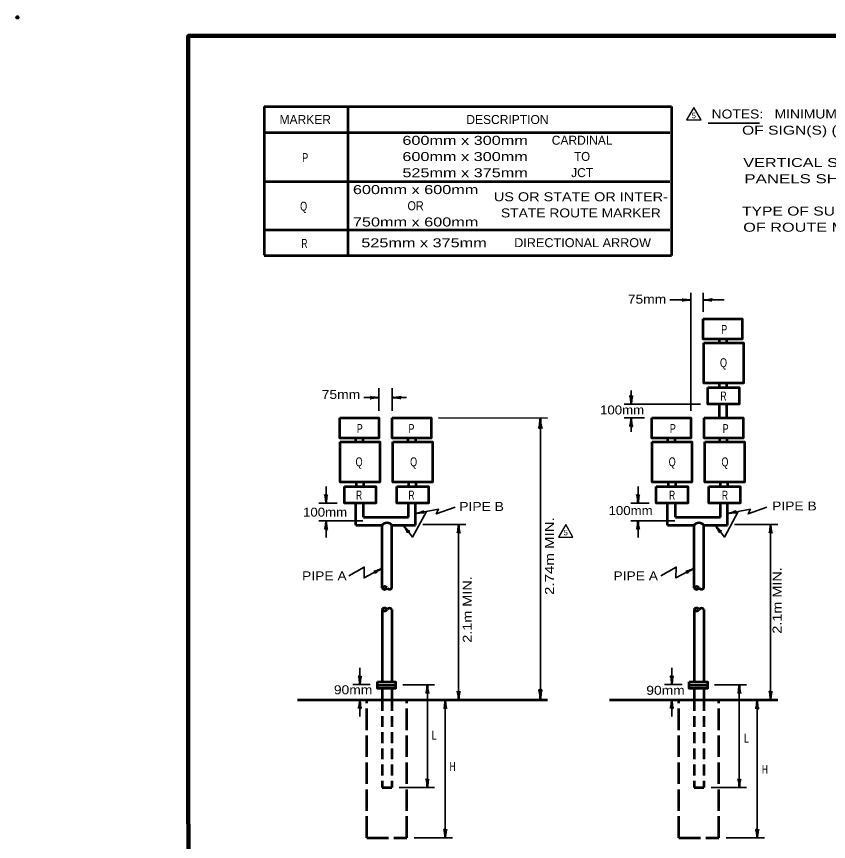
# Model space of a CAD drawing. Extents: x 11 to 867, y -284 to 260.
# Drawn here: x 11 to 281.9, y -14.9 to 260.4 of the extents above; entities that cross this region are included whole.
import ezdxf
from ezdxf.enums import TextEntityAlignment as Align

# ---------------------------------------------------------------- set-up
doc = ezdxf.new("R2010")
doc.units = 0
doc.header["$LTSCALE"] = 1.2
doc.header["$PDMODE"] = 32
doc.header["$PDSIZE"] = 0.6
doc.linetypes.add('LONG_DASHED', pattern=[7.5, 6, -1.5])
doc.linetypes.add('MEDIUM_DASHED', pattern=[4.5, 3, -1.5])
doc.layers.add('1', color=7, linetype='Continuous', lineweight=53)

msp = doc.modelspace()

# ---------------------------------------------------------------- linework, layer by layer
at = {"layer": '1'}
for p, q in [((93.586, 230.312), (229.546, 230.312)), ((93.586, 230.312), (93.586, 180.794)), ((121.568, 230.312), (121.568, 180.794)), ((229.546, 230.312), (229.546, 180.614)), ((93.586, 221.7), (228.998, 221.7)), ((93.586, 205.374), (228.998, 205.374)), ((93.586, 189.226), (228.998, 189.226)), ((93.586, 180.614), (229.546, 180.614)), ((245.475, 151.463), (245.475, 152.749)), ((247.983, 151.463), (247.983, 152.749)), ((245.475, 136.631), (245.475, 138.069)), ((247.983, 136.631), (247.983, 138.069)), ((245.475, 126.419), (245.475, 131.031)), ((247.983, 126.419), (247.983, 131.031)), ((124.065, 119.684), (124.065, 118.399)), ((126.573, 119.684), (126.573, 118.399)), ((141.567, 119.684), (141.567, 118.399)), ((144.075, 119.684), (144.075, 118.399)), ((228.121, 119.684), (228.121, 118.399)), ((230.629, 119.684), (230.629, 118.399)), ((245.475, 119.684), (245.475, 118.399)), ((247.983, 119.684), (247.983, 118.399)), ((124.301, 105.005), (124.301, 103.567)), ((126.745, 105.005), (126.745, 103.567)), ((141.803, 105.005), (141.803, 103.567)), ((144.247, 105.005), (144.247, 103.567)), ((228.357, 105.005), (228.357, 103.567)), ((230.801, 105.005), (230.801, 103.567)), ((245.711, 105.005), (245.711, 103.567)), ((248.155, 105.005), (248.155, 103.567)), ((124.163, 90.611), (124.163, 97.967)), ((126.767, 93.355), (126.767, 97.967)), ((141.737, 93.355), (141.737, 97.967)), ((144.099, 90.611), (144.099, 97.967)), ((228.219, 90.611), (228.219, 97.967)), ((230.823, 93.355), (230.823, 97.967)), ((245.793, 93.355), (245.793, 97.967)), ((248.155, 90.611), (248.155, 97.967)), ((126.767, 93.355), (141.737, 93.355)), ((230.823, 93.355), (245.793, 93.355)), ((124.163, 90.611), (132.961, 90.611)), ((132.961, 69.707), (132.961, 90.611)), ((136.235, 69.707), (136.235, 90.611)), ((136.235, 90.611), (144.073, 90.611)), ((228.219, 90.611), (237.017, 90.611)), ((237.017, 69.707), (237.017, 90.611)), ((240.291, 69.707), (240.291, 90.611)), ((240.291, 90.611), (248.129, 90.611)), ((132.963, 62.471), (132.963, 38.358)), ((136.235, 62.471), (136.235, 38.358)), ((237.019, 62.471), (237.019, 38.358)), ((240.291, 62.471), (240.291, 38.358)), ((131.377, 37.241), (137.431, 37.241)), ((132.963, 36.12), (132.963, 32.333)), ((136.235, 36.12), (136.235, 32.333)), ((235.433, 37.241), (241.487, 37.241)), ((237.019, 36.12), (237.019, 32.333)), ((240.291, 36.12), (240.291, 32.333)), ((104.717, 32.333), (188.153, 32.333)), ((208.773, 32.333), (264.953, 32.333))]:
    msp.add_line(p, q, dxfattribs=at)
at = {"layer": '1', "lineweight": 35}
for p, q in [((241.737, 224.852), (258.905, 224.852)), ((235.921, 128.819), (235.921, 168.204)), ((240.093, 161.883), (240.093, 168.204)), ((228.937, 165.805), (235.921, 165.805)), ((240.093, 165.805), (247.077, 165.805)), ((131.865, 128.819), (131.865, 136.394)), ((136.355, 128.819), (136.355, 136.394)), ((216.059, 131.031), (216.059, 135.62)), ((131.911, 133.219), (126.911, 133.219)), ((136.355, 133.219), (141.135, 133.219)), ((239.207, 131.031), (213.659, 131.031)), ((151.767, 126.414), (188.153, 126.346)), ((185.753, 126.346), (185.753, 32.333)), ((220.509, 126.419), (213.659, 126.419)), ((216.059, 121.829), (216.059, 126.419)), ((114.277, 97.999), (114.277, 103.499)), ((218.333, 97.999), (218.333, 103.499)), ((117.967, 97.967), (111.877, 97.967)), ((222.023, 97.967), (215.933, 97.967)), ((126.563, 92.038), (111.877, 92.038)), ((114.277, 86.538), (114.277, 92.038)), ((146.499, 90.861), (160.897, 90.861)), ((158.497, 32.333), (158.497, 90.861)), ((230.619, 92.038), (215.933, 92.038)), ((218.333, 86.538), (218.333, 92.038)), ((250.555, 90.861), (264.953, 90.861)), ((262.553, 32.333), (262.553, 90.861)), ((125.549, 37.489), (125.549, 43.001)), ((229.605, 37.489), (229.605, 43.001)), ((128.977, 37.489), (123.149, 37.489)), ((139.831, 37.381), (150.461, 37.381)), ((148.061, 37.381), (148.061, 3.099)), ((233.033, 37.489), (227.205, 37.489)), ((243.887, 37.381), (254.517, 37.381)), ((252.117, 37.381), (252.117, 3.099)), ((125.549, 26.821), (125.549, 32.333)), ((154.029, 32.206), (154.029, -13.726)), ((229.605, 26.821), (229.605, 32.333)), ((258.085, 32.206), (258.085, -13.726)), ((138.635, 3.099), (150.461, 3.099)), ((242.691, 3.099), (254.517, 3.099)), ((143.665, -13.726), (156.429, -13.726)), ((247.721, -13.726), (260.485, -13.726))]:
    msp.add_line(p, q, dxfattribs=at)
at = {"layer": '1', "linetype": 'LONG_DASHED'}
for p, q in [((127.901, -13.726), (127.901, 32.333)), ((141.265, -13.726), (141.265, 32.333)), ((231.957, -13.726), (231.957, 32.333)), ((245.321, -13.726), (245.321, 32.333)), ((127.901, -13.726), (141.265, -13.726)), ((231.957, -13.726), (245.321, -13.726))]:
    msp.add_line(p, q, dxfattribs=at)
at = {"layer": '1', "linetype": 'MEDIUM_DASHED'}
for p, q in [((132.963, 32.333), (132.963, 3.099)), ((136.235, 32.333), (136.235, 3.099)), ((237.019, 32.333), (237.019, 3.099)), ((240.291, 32.333), (240.291, 3.099)), ((132.963, 3.099), (136.235, 3.099)), ((237.019, 3.099), (240.291, 3.099))]:
    msp.add_line(p, q, dxfattribs=at)
at = {"layer": '1', "lineweight": 158}
msp.add_lwpolyline([(860.008, 254), (68.308, 253.9), (68.408, -272.101)], dxfattribs=at)
at = {"layer": '1', "lineweight": 25}
for points in [[(236.955, 230.033), (234.555, 225.876), (239.355, 225.876)], [(194.227, 90.844), (191.827, 86.687), (196.627, 86.687)]]:
    msp.add_lwpolyline(points, close=True, dxfattribs=at)
at = {"layer": '1'}
for points in [[(240.093, 159.483), (253.105, 159.483), (253.105, 152.749), (240.093, 152.749)], [(240.247, 151.463), (253.485, 151.463), (253.485, 138.069), (240.247, 138.069)], [(241.607, 136.631), (252.123, 136.631), (252.123, 131.031), (241.607, 131.031)], [(118.853, 126.419), (131.865, 126.419), (131.865, 119.684), (118.853, 119.684)], [(136.355, 126.419), (149.367, 126.419), (149.367, 119.684), (136.355, 119.684)], [(222.909, 126.419), (235.921, 126.419), (235.921, 119.684), (222.909, 119.684)], [(240.411, 126.419), (253.423, 126.419), (253.423, 119.684), (240.411, 119.684)], [(119.007, 118.399), (132.245, 118.399), (132.245, 105.005), (119.007, 105.005)], [(136.509, 118.399), (149.747, 118.399), (149.747, 105.005), (136.509, 105.005)], [(223.063, 118.399), (236.301, 118.399), (236.301, 105.005), (223.063, 105.005)], [(240.565, 118.399), (253.803, 118.399), (253.803, 105.005), (240.565, 105.005)], [(120.367, 103.567), (130.883, 103.567), (130.883, 97.967), (120.367, 97.967)], [(137.869, 103.567), (148.385, 103.567), (148.385, 97.967), (137.869, 97.967)], [(224.423, 103.567), (234.939, 103.567), (234.939, 97.967), (224.423, 97.967)], [(241.925, 103.567), (252.441, 103.567), (252.441, 97.967), (241.925, 97.967)], [(131.377, 38.358), (137.431, 38.358), (137.431, 36.12), (131.377, 36.12)], [(235.433, 38.358), (241.487, 38.358), (241.487, 36.12), (235.433, 36.12)]]:
    msp.add_lwpolyline(points, close=True, dxfattribs=at)
at = {"layer": '1', "lineweight": 35}
for points in [[(144.099, 94.532), (151.795, 95.969), (151.009, 94.397), (157.295, 96.689)], [(248.155, 94.532), (255.851, 95.969), (255.065, 94.397), (261.351, 96.689)], [(147.719, 95.209), (143.087, 86.669), (140.081, 90.611)], [(251.775, 95.209), (247.143, 86.669), (244.137, 90.611)], [(132.961, 76.264), (126.931, 73.031), (127.001, 76.654), (121.845, 73.727)], [(237.017, 76.264), (230.987, 73.031), (231.057, 76.654), (225.901, 73.727)]]:
    msp.add_lwpolyline(points, dxfattribs=at)
at = {"layer": '1'}
for centre, radius, start, end in [((134.598, 89.228), 2.143, 40.17606, 139.82394), ((238.654, 89.228), 2.143, 40.17606, 139.82394), ((133.781, 69.15), 0.989, 34.21419, 145.78581), ((133.781, 70.145), 0.928, 208.21086, 331.78914), ((135.417, 70.286), 1.003, 215.33373, 324.66627), ((237.837, 69.15), 0.989, 34.21419, 145.78581), ((237.837, 70.145), 0.928, 208.21086, 331.78914), ((239.473, 70.286), 1.003, 215.33373, 324.66627), ((133.781, 62.032), 0.928, 28.21086, 151.78914), ((133.781, 63.027), 0.989, 214.21419, 325.78581), ((135.417, 61.891), 1.003, 35.33373, 144.66627), ((237.837, 62.032), 0.928, 28.21086, 151.78914), ((237.837, 63.027), 0.989, 214.21419, 325.78581), ((239.473, 61.891), 1.003, 35.33373, 144.66627)]:
    msp.add_arc(centre, radius, start, end, dxfattribs=at)
at = {"layer": '1', "lineweight": 40}
for centre, major_axis, ratio, start_param, end_param in [((234.83, 165.528), (1.786, 0.156), 0.122415, 0.8963533, 3.1415927), ((234.8, 166.016), (1.756, -0.176), 0.07063, 3.1407148, 5.41811), ((241.213, 165.593), (-1.756, 0.176), 0.07063, 3.1407148, 5.41811), ((241.213, 165.593), (-1.756, 0.176), 0.07063, 3.1407148, 5.41811), ((241.184, 166.081), (-1.786, -0.156), 0.122415, 0.8963533, 3.1415927), ((241.184, 166.081), (-1.786, -0.156), 0.122415, 0.8963533, 3.1415927), ((130.82, 132.942), (1.786, 0.156), 0.122415, 0.8963533, 3.1415927), ((130.79, 133.43), (1.756, -0.176), 0.07063, 3.1407148, 5.41811), ((137.475, 133.007), (-1.756, 0.176), 0.07063, 3.1407148, 5.41811), ((137.446, 133.495), (-1.786, -0.156), 0.122415, 0.8963533, 3.1415927), ((215.783, 132.122), (0.156, -1.786), 0.122415, 0.8963533, 3.1415927), ((216.27, 132.151), (-0.176, -1.756), 0.07063, 3.1407148, 5.41811), ((185.499, 125.002), (0.211, 2.108), 0.07063, 3.1407148, 5.41811), ((185.499, 125.002), (0.211, 2.108), 0.07063, 3.1407148, 5.41811), ((186.084, 125.037), (-0.187, 2.143), 0.122415, 0.8963533, 3.1415927), ((186.084, 125.037), (-0.187, 2.143), 0.122415, 0.8963533, 3.1415927), ((215.847, 125.298), (0.176, 1.756), 0.07063, 3.1407148, 5.41811), ((216.335, 125.327), (-0.156, 1.786), 0.122415, 0.8963533, 3.1415927), ((114.001, 99.09), (0.156, -1.786), 0.122415, 0.8963533, 3.1415927), ((114.001, 99.09), (0.156, -1.786), 0.122415, 0.8963533, 3.1415927), ((114.488, 99.119), (-0.176, -1.756), 0.07063, 3.1407148, 5.41811), ((114.488, 99.119), (-0.176, -1.756), 0.07063, 3.1407148, 5.41811), ((218.057, 99.09), (0.156, -1.786), 0.122415, 0.8963533, 3.1415927), ((218.057, 99.09), (0.156, -1.786), 0.122415, 0.8963533, 3.1415927), ((218.544, 99.119), (-0.176, -1.756), 0.07063, 3.1407148, 5.41811), ((218.544, 99.119), (-0.176, -1.756), 0.07063, 3.1407148, 5.41811), ((145.121, 95.004), (-1.727, -0.481), 0.122415, 0.8963533, 3.1415927), ((145.121, 95.004), (-1.727, -0.481), 0.122415, 0.8963533, 3.1415927), ((145.239, 94.53), (-1.759, -0.15), 0.07063, 3.1407148, 5.41811), ((145.239, 94.53), (-1.759, -0.15), 0.07063, 3.1407148, 5.41811), ((249.177, 95.004), (-1.727, -0.481), 0.122415, 0.8963533, 3.1415927), ((249.177, 95.004), (-1.727, -0.481), 0.122415, 0.8963533, 3.1415927), ((249.295, 94.53), (-1.759, -0.15), 0.07063, 3.1407148, 5.41811), ((249.295, 94.53), (-1.759, -0.15), 0.07063, 3.1407148, 5.41811), ((114.065, 90.918), (0.176, 1.756), 0.07063, 3.1407148, 5.41811), ((114.553, 90.947), (-0.156, 1.786), 0.122415, 0.8963533, 3.1415927), ((158.285, 89.74), (0.176, 1.756), 0.07063, 3.1407148, 5.41811), ((158.773, 89.769), (-0.156, 1.786), 0.122415, 0.8963533, 3.1415927), ((218.121, 90.918), (0.176, 1.756), 0.07063, 3.1407148, 5.41811), ((218.609, 90.947), (-0.156, 1.786), 0.122415, 0.8963533, 3.1415927), ((262.341, 89.74), (0.176, 1.756), 0.07063, 3.1407148, 5.41811), ((262.829, 89.769), (-0.156, 1.786), 0.122415, 0.8963533, 3.1415927), ((140.592, 89.591), (-0.925, 1.503), 0.07063, 3.1407148, 5.41811), ((140.962, 89.91), (-1.207, 1.325), 0.122415, 0.8963533, 3.1415927), ((244.648, 89.591), (-0.925, 1.503), 0.07063, 3.1407148, 5.41811), ((245.018, 89.91), (-1.207, 1.325), 0.122415, 0.8963533, 3.1415927), ((131.873, 75.921), (1.631, 0.675), 0.07063, 3.1407148, 5.41811), ((132.13, 75.505), (1.5, 0.982), 0.122415, 0.8963533, 3.1415927), ((235.929, 75.921), (1.631, 0.675), 0.07063, 3.1407148, 5.41811), ((236.186, 75.505), (1.5, 0.982), 0.122415, 0.8963533, 3.1415927), ((125.273, 38.58), (0.156, -1.786), 0.122415, 0.8963533, 3.1415927), ((125.273, 38.58), (0.156, -1.786), 0.122415, 0.8963533, 3.1415927), ((125.76, 38.609), (-0.176, -1.756), 0.07063, 3.1407148, 5.41811), ((125.76, 38.609), (-0.176, -1.756), 0.07063, 3.1407148, 5.41811), ((229.329, 38.58), (0.156, -1.786), 0.122415, 0.8963533, 3.1415927), ((229.329, 38.58), (0.156, -1.786), 0.122415, 0.8963533, 3.1415927), ((229.816, 38.609), (-0.176, -1.756), 0.07063, 3.1407148, 5.41811), ((229.816, 38.609), (-0.176, -1.756), 0.07063, 3.1407148, 5.41811), ((147.849, 36.26), (0.176, 1.756), 0.07063, 3.1407148, 5.41811), ((147.849, 36.26), (0.176, 1.756), 0.07063, 3.1407148, 5.41811), ((148.337, 36.289), (-0.156, 1.786), 0.122415, 0.8963533, 3.1415927), ((148.337, 36.289), (-0.156, 1.786), 0.122415, 0.8963533, 3.1415927), ((185.421, 33.642), (0.187, -2.143), 0.122415, 0.8963533, 3.1415927), ((251.905, 36.26), (0.176, 1.756), 0.07063, 3.1407148, 5.41811), ((252.393, 36.289), (-0.156, 1.786), 0.122415, 0.8963533, 3.1415927), ((158.221, 33.424), (0.156, -1.786), 0.122415, 0.8963533, 3.1415927), ((158.708, 33.453), (-0.176, -1.756), 0.07063, 3.1407148, 5.41811), ((186.007, 33.677), (-0.211, -2.108), 0.07063, 3.1407148, 5.41811), ((262.277, 33.424), (0.156, -1.786), 0.122415, 0.8963533, 3.1415927), ((262.764, 33.453), (-0.176, -1.756), 0.07063, 3.1407148, 5.41811), ((125.337, 31.212), (0.176, 1.756), 0.07063, 3.1407148, 5.41811), ((125.825, 31.241), (-0.156, 1.786), 0.122415, 0.8963533, 3.1415927), ((153.817, 31.086), (0.176, 1.756), 0.07063, 3.1407148, 5.41811), ((153.817, 31.086), (0.176, 1.756), 0.07063, 3.1407148, 5.41811), ((154.305, 31.115), (-0.156, 1.786), 0.122415, 0.8963533, 3.1415927), ((154.305, 31.115), (-0.156, 1.786), 0.122415, 0.8963533, 3.1415927), ((229.393, 31.212), (0.176, 1.756), 0.07063, 3.1407148, 5.41811), ((229.881, 31.241), (-0.156, 1.786), 0.122415, 0.8963533, 3.1415927), ((257.873, 31.086), (0.176, 1.756), 0.07063, 3.1407148, 5.41811), ((258.361, 31.115), (-0.156, 1.786), 0.122415, 0.8963533, 3.1415927), ((147.785, 4.19), (0.156, -1.786), 0.122415, 0.8963533, 3.1415927), ((148.272, 4.219), (-0.176, -1.756), 0.07063, 3.1407148, 5.41811), ((251.841, 4.19), (0.156, -1.786), 0.122415, 0.8963533, 3.1415927), ((252.328, 4.219), (-0.176, -1.756), 0.07063, 3.1407148, 5.41811), ((153.753, -12.634), (0.156, -1.786), 0.122415, 0.8963533, 3.1415927), ((154.24, -12.605), (-0.176, -1.756), 0.07063, 3.1407148, 5.41811), ((257.809, -12.634), (0.156, -1.786), 0.122415, 0.8963533, 3.1415927), ((258.296, -12.605), (-0.176, -1.756), 0.07063, 3.1407148, 5.41811)]:
    msp.add_ellipse(centre, major_axis=major_axis, ratio=ratio, start_param=start_param, end_param=end_param, dxfattribs=at)
at = {"layer": '1'}
msp.add_point((11.308, 260.1), dxfattribs=at)

# ---------------------------------------------------------------- texts
for s, width, p in [('NOTES:   MINIMUM DISTANCE FROM GROUND TO TOP', 1.15, (242.888, 226.364)), ('       OF SIGN(S) (ALL 5 TYPES) IS 2.7m.', 1.3, (242.888, 220.964)), ('       VERTICAL SPACING BETWEEN P & Q AND Q & R', 1.35, (242.888, 210.164)), ('       PANELS SHALL BE (25mm).', 1.4, (242.888, 204.764)), ('       TYPE OF SUPPORT TO BE DETERMINED BY NUMBER', 1.3, (242.888, 193.964)), ('       OF ROUTE MARKER SHIELDS', 1.35, (242.888, 188.564))]:
    msp.add_text(s, height=3, dxfattribs=dict(at, width=width)).set_placement(p)
for s, p in [('MARKER', (107.323, 224.517)), ('DESCRIPTION', (174.771, 224.517)), ('CARDINAL', (199.695, 217.601)), ('JCT', (199.695, 206.801))]:
    msp.add_text(s, height=3, dxfattribs=at).set_placement(p, align=Align.CENTER)
for s, height, width, p in [('5', 1.8, 0.9, (236.955, 226.451)), ('600mm x 300mm', 3, 1.35, (160.65, 217.557)), ('P', 3, 0.75, (107.324, 211.799)), ('600mm x 300mm', 3, 1.35, (160.65, 212.157)), ('TO', 3, 0.95, (199.695, 212.201)), ('525mm x 375mm', 3, 1.35, (160.65, 206.757)), ('600mm x 600mm', 3, 1.35, (144.145, 201.135)), ('US OR STATE OR INTER-', 3, 1.2, (199.268, 198.747)), ('Q', 3, 0.75, (106.788, 195.601)), ('OR', 3, 0.9, (144.145, 195.735)), ('STATE ROUTE MARKER', 3, 1.15, (199.268, 193.347)), ('750mm x 600mm', 3, 1.35, (144.145, 190.335)), ('R', 3, 0.7, (107.056, 183.152)), ('525mm x 375mm', 3, 1.35, (146.943, 183.376)), ('DIRECTIONAL ARROW', 3, 1.05, (199.847, 183.419)), ('75mm', 3, 1.15, (221.339, 164.572)), ('P', 3, 0.75, (247.079, 154.462)), ('Q', 3, 0.75, (246.843, 143.353)), ('75mm', 3, 1.15, (119.244, 132.781)), ('R', 3, 0.7, (246.843, 132.244)), ('100mm', 3, 1.1, (213.015, 127.585)), ('P', 3, 0.75, (125.518, 121.377)), ('P', 3, 0.75, (142.767, 121.377)), ('P', 3, 0.75, (229.959, 121.384)), ('P', 3, 0.75, (247.566, 121.35)), ('Q', 3, 0.75, (125.281, 110.267)), ('Q', 3, 0.75, (143.476, 110.267)), ('Q', 3, 0.75, (229.722, 110.275)), ('Q', 3, 0.75, (247.329, 110.241)), ('R', 3, 0.7, (125.281, 99.158)), ('R', 3, 0.7, (142.767, 99.158)), ('R', 3, 0.7, (229.722, 99.165)), ('R', 3, 0.7, (247.33, 99.132)), ('100mm', 3, 1.1, (113.939, 93.485)), ('PIPE B', 3, 1.15, (166.16, 95.376)), ('100mm', 3, 1.1, (215.856, 94.018)), ('PIPE B', 3, 1.15, (270.493, 95.539)), ('5', 1.8, 0.9, (194.227, 87.262)), ('PIPE A', 3, 1.15, (113.703, 72.212)), ('PIPE A', 3, 1.15, (217.566, 72.213)), ('90mm', 3, 1.15, (123.281, 34.205)), ('90mm', 3, 1.15, (227.507, 34.028)), ('L', 3, 0.75, (150.328, 19.029)), ('L', 3, 0.75, (254.499, 18.055)), ('H', 3, 0.7, (156.472, 8.629)), ('H', 3, 0.7, (260.643, 7.655))]:
    msp.add_text(s, height=height, dxfattribs=dict(at, width=width)).set_placement(p, align=Align.CENTER)
for s, width, p in [('2.74m MIN.', 1.25, (190.295, 80.321)), ('2.1m MIN.', 1.2, (266.214, 65.517)), ('2.1m MIN.', 1.2, (162.878, 62.494))]:
    msp.add_text(s, height=3, rotation=90, dxfattribs=dict(at, width=width)).set_placement(p, align=Align.CENTER)

doc.saveas('drawing.dxf')
